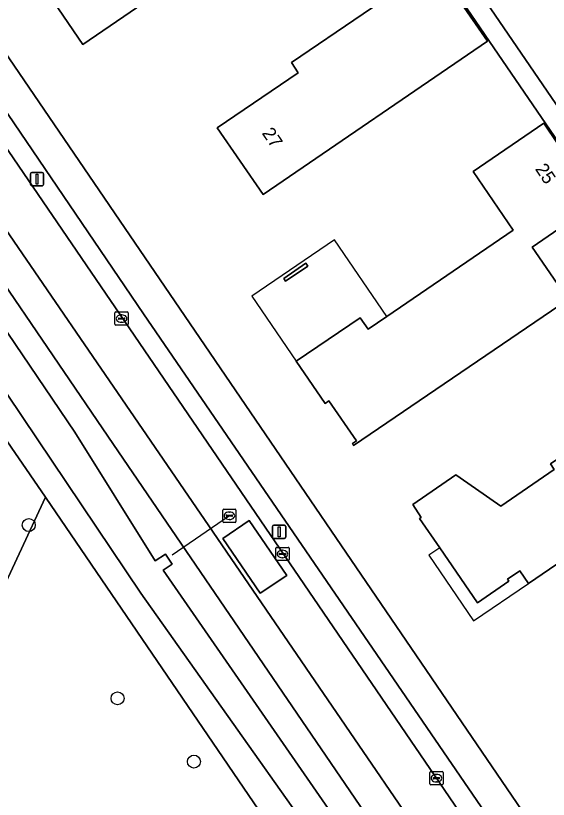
# Model space of a CAD drawing. Extents: x 155275 to 156265, y 382654 to 383635.
# Drawn here: x 155606.7 to 155646.9, y 383337.1 to 383396.1 of the extents above; entities that cross this region are included whole.
import ezdxf

# ---------------------------------------------------------------- set-up
doc = ezdxf.new("R2010")
doc.units = 0
for name, color, linetype in [('IMGEO_Boom', 7, 'Continuous'), ('IMGEO_Duiker', 7, 'Continuous'), ('IMGEO_Erf', 7, 'Continuous'), ('IMGEO_Gemengd_bos', 7, 'Continuous'), ('IMGEO_Groenvoorziening', 7, 'Continuous'), ('IMGEO_Haag', 7, 'Continuous'), ('IMGEO_Kolk', 7, 'Continuous'), ('IMGEO_Lichtmast', 7, 'Continuous'), ('IMGEO_Oever', 7, 'Continuous'), ('IMGEO_Pand', 7, 'Continuous'), ('IMGEO_Pand_nummerreeks', 7, 'Continuous'), ('IMGEO_Pand_overbouw', 7, 'Continuous'), ('IMGEO_Rijbaan_lokaal_gesloten', 7, 'Continuous'), ('IMGEO_Rijbaan_lokaal_open', 7, 'Continuous'), ('IMGEO_Rioolput', 7, 'Continuous'), ('IMGEO_Voetpad_open', 7, 'Continuous'), ('IMGEO_Waterloop', 7, 'Continuous')]:
    doc.layers.add(name, color=color, linetype=linetype)

msp = doc.modelspace()

# ---------------------------------------------------------------- linework, layer by layer
at = {"layer": 'IMGEO_Boom'}
for centre in [(155607.7, 383357.746), (155614.389, 383344.679), (155620.148, 383339.908)]:
    msp.add_circle(centre, 0.489, dxfattribs=at)
at = {"layer": 'IMGEO_Duiker'}
msp.add_lwpolyline([(155622.817, 383358.445), (155618.504, 383355.469)], dxfattribs=at)
at = {"layer": 'IMGEO_Erf'}
for points in [[(155626.344, 383411.364), (155605.932, 383397.438), (155603.987, 383396.057), (155605.754, 383393.471), (155605.827, 383393.52), (155653.992, 383322.86), (155654.882, 383321.57), (155677.497, 383337.038), (155680.25, 383338.906), (155654.839, 383376.063), (155629.299, 383413.395)], [(155621.307, 383397.58), (155619.94, 383399.584), (155611.775, 383393.983), (155608.422, 383398.907), (155624.655, 383410.016), (155627.904, 383405.256), (155628.359, 383405.565), (155629.83, 383403.396)], [(155625.365, 383382.665), (155621.893, 383387.683), (155628.009, 383391.842), (155627.505, 383392.602), (155638.312, 383399.989), (155642.265, 383394.224)], [(155632.183, 383363.753), (155632.091, 383363.899), (155632.39, 383364.102), (155630.323, 383367.106), (155630.036, 383366.909), (155627.855, 383370.095), (155632.678, 383373.378), (155633.279, 383372.507), (155634.699, 383373.478), (155644.215, 383379.981), (155641.198, 383384.398), (155646.515, 383388.036), (155650.539, 383382.066), (155645.636, 383378.694), (155648.345, 383374.745)], [(155628.734, 383377.263), (155627.056, 383376.132), (155626.917, 383376.34), (155628.593, 383377.479)], [(155647.303, 383361.927), (155647.013, 383362.352), (155649.769, 383364.231), (155650.055, 383363.812), (155658.911, 383369.873), (155659.212, 383369.426), (155662.297, 383364.905), (155645.369, 383353.349), (155644.717, 383354.302), (155643.781, 383353.657), (155643.882, 383353.509), (155641.508, 383351.891), (155638.669, 383356.028), (155637.151, 383358.24), (155637.284, 383358.325), (155636.638, 383359.304), (155639.894, 383361.521), (155641.364, 383360.503), (155643.288, 383359.179)]]:
    msp.add_lwpolyline(points, close=True, dxfattribs=at)
at = {"layer": 'IMGEO_Gemengd_bos'}
msp.add_lwpolyline([(155595.424, 383343.49), (155596.747, 383344.573), (155604.968, 383351.306), (155608.956, 383359.839), (155596.262, 383378.284), (155590.187, 383378.284), (155594.521, 383347.231)], dxfattribs=at)
at = {"layer": 'IMGEO_Groenvoorziening'}
for points in [[(155616.345, 383373.664), (155603.776, 383392.148), (155602.488, 383391.286), (155603.246, 383390.171), (155650.33, 383321.209), (155651.739, 383319.271)], [(155643.355, 383309.466), (155646.237, 383311.445), (155649.735, 383313.591), (155650.511, 383314.925), (155647.53, 383319.282), (155621.26, 383357.689), (155600.322, 383388.244), (155599.168, 383389.876)], [(155600.406, 383383.858), (155614.076, 383363.825), (155644.305, 383319.503)], [(155655.279, 383316.791), (155616.345, 383373.664)], [(155639.927, 383314.384), (155608.956, 383359.839), (155604.968, 383351.306), (155596.747, 383344.573), (155595.424, 383343.49)]]:
    msp.add_lwpolyline(points, dxfattribs=at)
at = {"layer": 'IMGEO_Haag'}
for points in [[(155616.345, 383373.664), (155603.776, 383392.148), (155602.488, 383391.286), (155603.246, 383390.171), (155650.33, 383321.209), (155651.739, 383319.271)], [(155655.279, 383316.791), (155616.345, 383373.664)]]:
    msp.add_lwpolyline(points, dxfattribs=at)
at = {"layer": 'IMGEO_Kolk'}
for p, q in [((155614.192, 383372.883), (155614.192, 383373.735)), ((155614.267, 383373.809), (155615.119, 383373.809)), ((155614.68, 383373.589), (155614.705, 383373.589)), ((155615.193, 383373.735), (155615.193, 383372.883)), ((155614.451, 383373.303), (155614.451, 383373.315)), ((155614.889, 383373.266), (155614.491, 383373.266)), ((155614.494, 383373.352), (155614.892, 383373.352)), ((155614.703, 383373.029), (155614.678, 383373.029)), ((155614.935, 383373.315), (155614.935, 383373.303)), ((155615.119, 383372.809), (155614.267, 383372.809)), ((155626.319, 383355.137), (155626.319, 383355.989)), ((155626.394, 383356.063), (155627.246, 383356.063)), ((155626.807, 383355.843), (155626.832, 383355.843)), ((155627.32, 383355.989), (155627.32, 383355.137)), ((155626.578, 383355.557), (155626.578, 383355.569)), ((155627.016, 383355.52), (155626.618, 383355.52)), ((155626.621, 383355.606), (155627.019, 383355.606)), ((155626.83, 383355.283), (155626.805, 383355.283)), ((155627.062, 383355.569), (155627.062, 383355.557)), ((155627.246, 383355.063), (155626.394, 383355.063)), ((155637.923, 383338.238), (155637.923, 383339.09)), ((155637.998, 383339.164), (155638.85, 383339.164)), ((155638.182, 383338.658), (155638.182, 383338.67)), ((155638.62, 383338.621), (155638.222, 383338.621)), ((155638.225, 383338.707), (155638.623, 383338.707)), ((155638.411, 383338.944), (155638.436, 383338.944)), ((155638.666, 383338.67), (155638.666, 383338.658)), ((155638.924, 383339.09), (155638.924, 383338.238)), ((155638.85, 383338.164), (155637.998, 383338.164)), ((155638.434, 383338.384), (155638.409, 383338.384))]:
    msp.add_line(p, q, dxfattribs=at)
for points in [[(155614.192, 383372.883), (155614.192, 383373.735)], [(155614.267, 383373.809), (155615.119, 383373.809)], [(155615.193, 383373.735), (155615.193, 383372.883)], [(155615.119, 383372.809), (155614.267, 383372.809)], [(155626.319, 383355.137), (155626.319, 383355.989)], [(155626.394, 383356.063), (155627.246, 383356.063)], [(155627.32, 383355.989), (155627.32, 383355.137)], [(155627.246, 383355.063), (155626.394, 383355.063)], [(155637.923, 383338.238), (155637.923, 383339.09)], [(155637.998, 383339.164), (155638.85, 383339.164)], [(155638.924, 383339.09), (155638.924, 383338.238)], [(155638.85, 383338.164), (155637.998, 383338.164)]]:
    msp.add_lwpolyline(points, dxfattribs=at)
for centre, radius, start, end in [((155614.269, 383373.733), 0.0765, 91.55205, 178.44795), ((155614.269, 383373.733), 0.0765, 91.55205, 178.44795), ((155615.117, 383373.733), 0.0765, 1.55205, 88.44795), ((155615.117, 383373.733), 0.0765, 1.55205, 88.44795), ((155614.269, 383372.885), 0.0765, 181.55205, 268.44795), ((155614.269, 383372.885), 0.0765, 181.55205, 268.44795), ((155614.491, 383373.312), 0.0403, 85.87752, 175.75265), ((155614.488, 383373.302), 0.0366, 178.93798, 274.71019), ((155614.892, 383373.309), 0.043, 264.86636, 352.45326), ((155614.896, 383373.314), 0.0386, 1.73085, 96.63898), ((155615.117, 383372.885), 0.0765, 271.55205, 358.44795), ((155615.117, 383372.885), 0.0765, 271.55205, 358.44795), ((155626.396, 383355.987), 0.0765, 91.55205, 178.44795), ((155626.396, 383355.987), 0.0765, 91.55205, 178.44795), ((155627.244, 383355.987), 0.0765, 1.55205, 88.44795), ((155627.244, 383355.987), 0.0765, 1.55205, 88.44795), ((155626.618, 383355.566), 0.0403, 85.87752, 175.75265), ((155626.615, 383355.556), 0.0366, 178.93798, 274.71019), ((155627.019, 383355.563), 0.043, 264.86636, 352.45326), ((155627.023, 383355.568), 0.0386, 1.73085, 96.63898), ((155626.396, 383355.139), 0.0765, 181.55205, 268.44795), ((155626.396, 383355.139), 0.0765, 181.55205, 268.44795), ((155627.244, 383355.139), 0.0765, 271.55205, 358.44795), ((155627.244, 383355.139), 0.0765, 271.55205, 358.44795), ((155638, 383339.088), 0.0765, 91.55205, 178.44795), ((155638, 383339.088), 0.0765, 91.55205, 178.44795), ((155638.222, 383338.667), 0.0403, 85.87752, 175.75265), ((155638.219, 383338.657), 0.0366, 178.93798, 274.71019), ((155638.623, 383338.664), 0.043, 264.86636, 352.45326), ((155638.627, 383338.669), 0.0386, 1.73085, 96.63898), ((155638.848, 383339.088), 0.0765, 1.55205, 88.44795), ((155638.848, 383339.088), 0.0765, 1.55205, 88.44795), ((155638, 383338.24), 0.0765, 181.55205, 268.44795), ((155638, 383338.24), 0.0765, 181.55205, 268.44795), ((155638.848, 383338.24), 0.0765, 271.55205, 358.44795), ((155638.848, 383338.24), 0.0765, 271.55205, 358.44795)]:
    msp.add_arc(centre, radius, start, end, dxfattribs=at)
for centre, major_axis, ratio, start_param, end_param in [((155614.679, 383373.309), (-0.387, 0.002), 0.722429, 4.712389, 7.853982), ((155614.704, 383373.309), (-0.39, 0.002), 0.717154, 1.570796, 4.712389), ((155626.806, 383355.563), (-0.387, 0.002), 0.722429, 4.712389, 7.853982), ((155626.831, 383355.563), (-0.39, 0.002), 0.717154, 1.570796, 4.712389), ((155638.41, 383338.664), (-0.387, 0.002), 0.722429, 4.712389, 7.853982), ((155638.435, 383338.664), (-0.39, 0.002), 0.717154, 1.570796, 4.712389)]:
    msp.add_ellipse(centre, major_axis=major_axis, ratio=ratio, start_param=start_param, end_param=end_param, dxfattribs=at)
at = {"layer": 'IMGEO_Lichtmast'}
for p, q in [((155607.824, 383383.427), (155607.824, 383384.227)), ((155607.824, 383384.227), (155607.824, 383383.427)), ((155607.924, 383384.327), (155608.714, 383384.327)), ((155608.714, 383384.327), (155607.924, 383384.327)), ((155608.814, 383384.227), (155608.814, 383383.427)), ((155608.814, 383383.427), (155608.814, 383384.227)), ((155608.714, 383383.327), (155607.924, 383383.327)), ((155607.924, 383383.327), (155608.714, 383383.327)), ((155626.074, 383356.837), (155626.074, 383357.637)), ((155626.074, 383357.637), (155626.074, 383356.837)), ((155626.174, 383357.737), (155626.964, 383357.737)), ((155626.964, 383357.737), (155626.174, 383357.737)), ((155627.064, 383357.637), (155627.064, 383356.837)), ((155627.064, 383356.837), (155627.064, 383357.637)), ((155626.964, 383356.737), (155626.174, 383356.737)), ((155626.174, 383356.737), (155626.964, 383356.737))]:
    msp.add_line(p, q, dxfattribs=at)
for points in [[(155608.244, 383384.202), (155608.394, 383384.202), (155608.394, 383383.452), (155608.244, 383383.452), (155608.244, 383384.202)], [(155626.494, 383357.612), (155626.644, 383357.612), (155626.644, 383356.862), (155626.494, 383356.862), (155626.494, 383357.612)]]:
    msp.add_lwpolyline(points, dxfattribs=at)
for centre, start, end in [((155607.924, 383384.227), 90, 180), ((155607.924, 383384.227), 90, 180), ((155608.714, 383384.227), 0, 90), ((155608.714, 383384.227), 360, 90), ((155607.924, 383383.427), 180, 270), ((155607.924, 383383.427), 180, 270), ((155608.714, 383383.427), 270, 0), ((155608.714, 383383.427), 270, 0), ((155626.174, 383357.637), 90, 180), ((155626.174, 383357.637), 90, 180), ((155626.964, 383357.637), 0, 90), ((155626.964, 383357.637), 360, 90), ((155626.174, 383356.837), 180, 270), ((155626.174, 383356.837), 180, 270), ((155626.964, 383356.837), 270, 0), ((155626.964, 383356.837), 270, 0)]:
    msp.add_arc(centre, 0.1, start, end, dxfattribs=at)
at = {"layer": 'IMGEO_Oever'}
for points in [[(155597.044, 383385.573), (155611.166, 383364.754), (155617.232, 383355.058), (155618.005, 383355.55), (155618.496, 383354.801), (155617.817, 383354.332), (155637.513, 383325.925), (155643.133, 383317.634), (155643.25, 383317.025), (155644.562, 383315.011)], [(155644.562, 383315.011), (155643.274, 383314.145), (155642.126, 383315.831), (155641.658, 383316.077), (155635.218, 383325.667), (155616.154, 383352.599), (155594.89, 383384.215)], [(155644.305, 383319.503), (155614.076, 383363.825), (155600.406, 383383.858)], [(155594.875, 383380.299), (155596.262, 383378.284), (155608.956, 383359.839), (155639.927, 383314.384)]]:
    msp.add_lwpolyline(points, dxfattribs=at)
at = {"layer": 'IMGEO_Pand'}
for points in [[(155624.655, 383410.016), (155608.422, 383398.907), (155611.775, 383393.983), (155619.94, 383399.584), (155621.307, 383397.58), (155629.83, 383403.396), (155628.359, 383405.565), (155627.904, 383405.256)], [(155625.365, 383382.665), (155642.265, 383394.224), (155638.312, 383399.989), (155627.505, 383392.602), (155628.009, 383391.842), (155621.893, 383387.683)], [(155645.636, 383378.694), (155650.539, 383382.066), (155646.515, 383388.036), (155641.198, 383384.398), (155644.215, 383379.981), (155634.699, 383373.478), (155633.279, 383372.507), (155632.678, 383373.378), (155627.855, 383370.095), (155630.036, 383366.909), (155630.323, 383367.106), (155632.39, 383364.102), (155632.091, 383363.899), (155632.183, 383363.753), (155648.345, 383374.745)], [(155628.734, 383377.263), (155628.593, 383377.479), (155626.917, 383376.34), (155627.056, 383376.132)], [(155662.297, 383364.905), (155659.212, 383369.426), (155658.911, 383369.873), (155650.055, 383363.812), (155649.769, 383364.231), (155647.013, 383362.352), (155647.303, 383361.927), (155643.288, 383359.179), (155641.364, 383360.503), (155639.894, 383361.521), (155636.638, 383359.304), (155637.284, 383358.325), (155637.151, 383358.24), (155638.669, 383356.028), (155641.508, 383351.891), (155643.882, 383353.509), (155643.781, 383353.657), (155644.717, 383354.302), (155645.369, 383353.349)]]:
    msp.add_lwpolyline(points, close=True, dxfattribs=at)
at = {"layer": 'IMGEO_Pand_overbouw'}
for points in [[(155624.502, 383374.994), (155627.855, 383370.095), (155632.678, 383373.378), (155633.279, 383372.507), (155634.699, 383373.478), (155630.737, 383379.257)], [(155638.669, 383356.028), (155637.853, 383355.471), (155641.23, 383350.513), (155645.369, 383353.349), (155644.717, 383354.302), (155643.781, 383353.657), (155643.882, 383353.509), (155641.508, 383351.891)]]:
    msp.add_lwpolyline(points, close=True, dxfattribs=at)
at = {"layer": 'IMGEO_Rijbaan_lokaal_gesloten'}
for points in [[(155621.26, 383357.689), (155647.53, 383319.282), (155650.33, 383321.209), (155603.246, 383390.171), (155600.322, 383388.244)], [(155625.151, 383352.605), (155622.331, 383356.727), (155624.321, 383358.093), (155627.138, 383353.947)]]:
    msp.add_lwpolyline(points, close=True, dxfattribs=at)
at = {"layer": 'IMGEO_Rijbaan_lokaal_open'}
msp.add_lwpolyline([(155629.214, 383416.139), (155630.534, 383414.209), (155681.461, 383339.737), (155682.726, 383337.887)], dxfattribs=at)
msp.add_lwpolyline([(155625.151, 383352.605), (155627.138, 383353.947), (155624.321, 383358.093), (155622.331, 383356.727)], close=True, dxfattribs=at)
at = {"layer": 'IMGEO_Rioolput'}
for p, q in [((155622.316, 383358.019), (155622.316, 383358.871)), ((155622.391, 383358.945), (155623.243, 383358.945)), ((155622.804, 383358.725), (155622.829, 383358.725)), ((155623.317, 383358.871), (155623.317, 383358.019)), ((155622.575, 383358.439), (155622.575, 383358.451)), ((155623.013, 383358.402), (155622.615, 383358.402)), ((155622.618, 383358.488), (155623.016, 383358.488)), ((155622.827, 383358.165), (155622.802, 383358.165)), ((155623.059, 383358.451), (155623.059, 383358.439)), ((155623.243, 383357.945), (155622.391, 383357.945))]:
    msp.add_line(p, q, dxfattribs=at)
for points in [[(155622.316, 383358.019), (155622.316, 383358.871)], [(155622.391, 383358.945), (155623.243, 383358.945)], [(155623.317, 383358.871), (155623.317, 383358.019)], [(155623.243, 383357.945), (155622.391, 383357.945)]]:
    msp.add_lwpolyline(points, dxfattribs=at)
for centre, radius, start, end in [((155622.393, 383358.869), 0.0765, 91.55205, 178.44795), ((155622.393, 383358.869), 0.0765, 91.55205, 178.44795), ((155623.241, 383358.869), 0.0765, 1.55205, 88.44795), ((155623.241, 383358.869), 0.0765, 1.55205, 88.44795), ((155622.615, 383358.448), 0.0403, 85.87752, 175.75265), ((155622.612, 383358.438), 0.0366, 178.93798, 274.71019), ((155623.016, 383358.445), 0.043, 264.86636, 352.45326), ((155623.02, 383358.45), 0.0386, 1.73085, 96.63898), ((155622.393, 383358.021), 0.0765, 181.55205, 268.44795), ((155622.393, 383358.021), 0.0765, 181.55205, 268.44795), ((155623.241, 383358.021), 0.0765, 271.55205, 358.44795), ((155623.241, 383358.021), 0.0765, 271.55205, 358.44795)]:
    msp.add_arc(centre, radius, start, end, dxfattribs=at)
for centre, major_axis, ratio, start_param, end_param in [((155622.803, 383358.445), (-0.387, 0.002), 0.722429, 4.712389, 7.853982), ((155622.828, 383358.445), (-0.39, 0.002), 0.717154, 1.570796, 4.712389)]:
    msp.add_ellipse(centre, major_axis=major_axis, ratio=ratio, start_param=start_param, end_param=end_param, dxfattribs=at)
at = {"layer": 'IMGEO_Voetpad_open'}
msp.add_lwpolyline([(155630.534, 383414.209), (155629.299, 383413.395), (155654.839, 383376.063), (155680.25, 383338.906), (155681.461, 383339.737)], close=True, dxfattribs=at)
for points in [[(155605.827, 383393.52), (155605.754, 383393.471), (155603.776, 383392.148), (155616.345, 383373.664), (155655.279, 383316.791)], [(155658.21, 383316.737), (155658.043, 383316.991), (155655.599, 383320.531), (155654.882, 383321.57), (155653.992, 383322.86), (155605.827, 383393.52)]]:
    msp.add_lwpolyline(points, dxfattribs=at)
at = {"layer": 'IMGEO_Waterloop'}
for points in [[(155644.562, 383315.011), (155643.25, 383317.025), (155643.133, 383317.634), (155637.513, 383325.925), (155617.817, 383354.332), (155618.496, 383354.801), (155618.005, 383355.55), (155617.232, 383355.058), (155611.166, 383364.754), (155597.044, 383385.573)], [(155594.89, 383384.215), (155616.154, 383352.599), (155635.218, 383325.667), (155641.658, 383316.077), (155642.126, 383315.831), (155643.274, 383314.145), (155644.562, 383315.011)]]:
    msp.add_lwpolyline(points, dxfattribs=at)

# ---------------------------------------------------------------- texts
at = {"layer": 'IMGEO_Pand_nummerreeks'}
for s, rotation, p in [('27', 304.67653, (155625.233, 383387.285)), ('25', 303.78138, (155645.827, 383384.589))]:
    msp.add_text(s, height=1, rotation=rotation, dxfattribs=at).set_placement(p)

doc.saveas('drawing.dxf')
